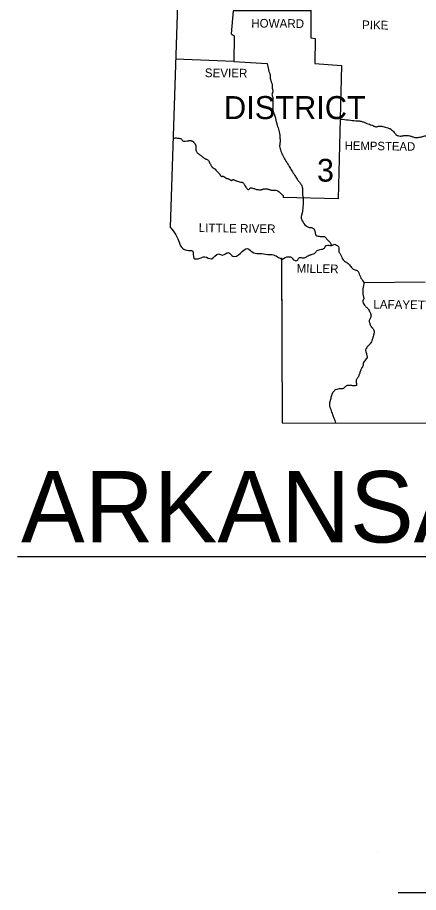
# Model space of a CAD drawing. Extents: x 164 to 3385, y 68 to 2119.
# Drawn here: x 2642.6 to 2834.9, y 1208.2 to 1627.9 of the extents above; entities that cross this region are included whole.
import ezdxf

# ---------------------------------------------------------------- set-up
doc = ezdxf.new("R2010")
doc.units = 0
for name, color, linetype in [('1', 7, 'Continuous'), ('2', 7, 'Continuous'), ('Default', 7, 'Continuous')]:
    doc.layers.add(name, color=color, linetype=linetype)

msp = doc.modelspace()

# ---------------------------------------------------------------- linework, layer by layer
at = {"layer": '1'}
for p, q in [((2642.58, 1369.37), (3267.14, 1369.37)), ((2815.36, 1227.78), (2815.36, 1227.78)), ((2825.14, 1208.22), (3138.23, 1208.22))]:
    msp.add_line(p, q, dxfattribs=at)
for points in [[(2769.26, 1512.61), (2769.46, 1433.46), (3128.04, 1432.87)], [(2769.26, 1511.75), (2769.46, 1433.46), (3124.12, 1432.88)]]:
    msp.add_lwpolyline(points, dxfattribs=at)
at = {"layer": 'Default'}
for points in [[(2704.43, 1950.7), (2724.46, 1789.87), (2715.75, 1527.33)], [(2811.49, 1730.41), (2811.36, 1690.77), (2806.52, 1690.68), (2806.91, 1687.77), (2802.26, 1687.87), (2802.16, 1685.74), (2797.62, 1685.74), (2797.71, 1684.19), (2790.94, 1684), (2790.84, 1678.1), (2784.26, 1678.68), (2783.2, 1631.07), (2745.94, 1631.16), (2745.07, 1620.13), (2746.42, 1619.16), (2746.33, 1606.78), (2718.43, 1608)], [(2783.2, 1631.07), (2783.2, 1618.2), (2785.33, 1617.81), (2785.13, 1605.81), (2797.91, 1604.84), (2796.36, 1540.88), (2770.04, 1541.55)], [(2746.33, 1606.78), (2762.39, 1605.81)], [(2769.26, 1511.75), (2769.46, 1433.46), (3124.12, 1432.88)], [(2838.16, 1501.01), (2808.84, 1500.72)]]:
    msp.add_lwpolyline(points, dxfattribs=at)
for points in [[(2762.39, 1605.81), (2762.88, 1602.91), (2763.06, 1602.27), (2763.3, 1601.64), (2763.55, 1601.02), (2763.75, 1600.39), (2763.81, 1599.91), (2763.81, 1599.42), (2763.8, 1598.93), (2763.84, 1598.45), (2764.04, 1597.73), (2764.3, 1597.01), (2764.56, 1596.29), (2764.71, 1595.55), (2764.71, 1594.49), (2764.77, 1593.95), (2764.86, 1593.42), (2764.95, 1592.89), (2765, 1592.36), (2764.95, 1592.06), (2764.82, 1591.78), (2764.68, 1591.49), (2764.62, 1591.2), (2764.7, 1590.62), (2764.87, 1590.04), (2765.04, 1589.46), (2765.1, 1588.87), (2765, 1587.13), (2765, 1585.68), (2765.1, 1583.26), (2765.23, 1582.71), (2765.45, 1582.19), (2765.69, 1581.67), (2765.88, 1581.13), (2766.65, 1577.94), (2767.13, 1576.29), (2767.91, 1573.78), (2768.39, 1570.68), (2768.49, 1568.36), (2768.46, 1567.83), (2768.38, 1567.29), (2768.31, 1566.76), (2768.29, 1566.23), (2768.88, 1563.81), (2769.94, 1561.39), (2771.29, 1559.07), (2772.94, 1556.46), (2774.1, 1554.42), (2775.55, 1552.2), (2776.71, 1550.36), (2777.13, 1549.77), (2777.57, 1549.2), (2778.03, 1548.63), (2778.46, 1548.04), (2779.23, 1546.1), (2779.27, 1545.42), (2779.25, 1544.75), (2779.21, 1544.07), (2779.23, 1543.39), (2779.33, 1542.76), (2779.45, 1542.14), (2779.57, 1541.51), (2779.62, 1540.88), (2779.52, 1538.07), (2779.33, 1535.55), (2779.19, 1534.68), (2778.98, 1533.8), (2778.77, 1532.94), (2778.65, 1532.07), (2779.13, 1530.42), (2780.97, 1528.01), (2782.13, 1527.33), (2782.63, 1527.21), (2783.16, 1527.19), (2783.68, 1527.14), (2784.17, 1526.94), (2784.73, 1526.32), (2785.13, 1525.59), (2785.28, 1525.08), (2785.32, 1524.52), (2785.41, 1523.99), (2785.53, 1523.76), (2785.71, 1523.55), (2786.7, 1523.08), (2787.75, 1522.88), (2788.03, 1522.85), (2788.33, 1522.86), (2788.93, 1522.92), (2789.5, 1522.92), (2789.97, 1522.68), (2791.04, 1521.52), (2792.49, 1519.97), (2793.2, 1518.61)], [(2797.29, 1579.19), (2801.39, 1578.81), (2804.78, 1578.42), (2806.09, 1578.32), (2806.74, 1578.25), (2807.07, 1578.2), (2807.39, 1578.13), (2808.08, 1577.93), (2808.76, 1577.68), (2810.1, 1577.16), (2812.52, 1576.29), (2812.91, 1576.13), (2813.29, 1575.95), (2813.67, 1575.77), (2814.07, 1575.62), (2814.71, 1575.55), (2815.37, 1575.66), (2816.03, 1575.8), (2816.68, 1575.81), (2817.79, 1575.6), (2818.91, 1575.33), (2820.19, 1574.98), (2820.82, 1574.76), (2821.12, 1574.62), (2821.42, 1574.46), (2822.39, 1573.68), (2823.26, 1572.81), (2823.54, 1572.5), (2823.79, 1572.17), (2824.42, 1571.55), (2824.96, 1571.26), (2825.52, 1571.11), (2826.65, 1571.07), (2827.11, 1571.12), (2827.57, 1571.22), (2828.03, 1571.32), (2828.49, 1571.36), (2830.71, 1571.16), (2831.35, 1570.99), (2831.97, 1570.76), (2832.59, 1570.53), (2833.23, 1570.39), (2833.73, 1570.35), (2834.25, 1570.35), (2835.26, 1570.49), (2836.9, 1570.87), (2838.84, 1571.36), (2840.05, 1571.55), (2840.66, 1571.57), (2841.26, 1571.55), (2841.72, 1571.48), (2842.18, 1571.37), (2842.63, 1571.25), (2843.1, 1571.16), (2844.31, 1571.09), (2845.52, 1571.07), (2846.22, 1571.12), (2846.92, 1571.24), (2847.62, 1571.34), (2847.97, 1571.36), (2848.32, 1571.36), (2849.04, 1571.27), (2851.15, 1570.66), (2852.52, 1570.07), (2853.87, 1569.46)], [(2717.17, 1570.04), (2718.14, 1570.13), (2719.14, 1570.11), (2720.08, 1570), (2720.88, 1569.81), (2721.23, 1569.54), (2721.55, 1569.1), (2721.91, 1568.7), (2722.33, 1568.55), (2723.2, 1568.65), (2724.75, 1568.84), (2725.11, 1568.87), (2725.47, 1568.87), (2725.84, 1568.83), (2726.2, 1568.75), (2726.51, 1568.6), (2726.78, 1568.4), (2727.03, 1568.15), (2727.26, 1567.87), (2727.56, 1567.51), (2727.81, 1567.14), (2728.01, 1566.75), (2728.14, 1566.33), (2728.15, 1565.96), (2728.11, 1565.6), (2728.05, 1565.24), (2728.04, 1564.87), (2728.14, 1564.29), (2728.25, 1563.95), (2728.39, 1563.61), (2728.81, 1563.04), (2729.97, 1562.07), (2731.23, 1561.1), (2732.39, 1560.33), (2732.65, 1560.18), (2732.92, 1560.05), (2733.47, 1559.8), (2733.97, 1559.5), (2734.33, 1559.07), (2734.52, 1558.68), (2735.3, 1557.13), (2735.73, 1556.47), (2735.98, 1556.16), (2736.26, 1555.88), (2736.54, 1555.66), (2736.85, 1555.49), (2737.15, 1555.32), (2737.43, 1555.1), (2738.68, 1553.75), (2739.26, 1553.17), (2739.52, 1552.84), (2739.73, 1552.48), (2739.95, 1552.12), (2740.08, 1551.96), (2740.23, 1551.81), (2740.47, 1551.72), (2740.75, 1551.73), (2741.04, 1551.76), (2741.3, 1551.71), (2741.66, 1551.51), (2742.02, 1551.27), (2742.37, 1551.03), (2742.75, 1550.84), (2743.01, 1550.76), (2743.28, 1550.69), (2743.55, 1550.63), (2743.81, 1550.55), (2744.11, 1550.39), (2744.39, 1550.16), (2744.67, 1549.94), (2744.97, 1549.78), (2745.26, 1549.81), (2745.55, 1549.97), (2745.85, 1550.14), (2746.13, 1550.17), (2746.5, 1550.03), (2746.86, 1549.87), (2747.22, 1549.72), (2747.59, 1549.59), (2749.52, 1549), (2749.79, 1548.96), (2750.07, 1548.95), (2750.46, 1548.88), (2750.53, 1548.85), (2750.59, 1548.81), (2750.99, 1548.41), (2751.29, 1547.94), (2751.55, 1547.45), (2751.69, 1547.2), (2751.84, 1546.97), (2752.44, 1546.17), (2752.76, 1545.79), (2753.1, 1545.42), (2753.27, 1545.35), (2753.45, 1545.4), (2753.83, 1545.74), (2754.23, 1546.14), (2754.44, 1546.27), (2754.65, 1546.29), (2755.37, 1546.11), (2756.09, 1545.84), (2756.81, 1545.59), (2757.55, 1545.42), (2758.47, 1545.33), (2759.39, 1545.33), (2759.81, 1545.42), (2760.21, 1545.58), (2760.62, 1545.73), (2761.04, 1545.81), (2762.3, 1545.71), (2762.88, 1545.58), (2763.46, 1545.42), (2764.04, 1545.26), (2764.62, 1545.13), (2764.98, 1545.11), (2765.34, 1545.13), (2765.71, 1545.16), (2766.07, 1545.13), (2767.62, 1544.55), (2769.07, 1543.39), (2770.04, 1542.13), (2770.04, 1541.55)], [(2715.75, 1527.33), (2718.56, 1523.65), (2719.72, 1521.04), (2721.36, 1517.65), (2723.78, 1516.3), (2726.59, 1515.81), (2727.17, 1512.52), (2730.07, 1512.43), (2732.39, 1513.1), (2735.59, 1512.23), (2738.97, 1514.55), (2740.91, 1513.97), (2743.72, 1515.13), (2745.84, 1513.39), (2749.52, 1514.94), (2752.81, 1517.07), (2755.91, 1515.04), (2758.91, 1514.75), (2762.49, 1514.26), (2765.3, 1514.07), (2767.81, 1512.81), (2769.08, 1511.94), (2769.26, 1511.75)], [(2769.26, 1511.75), (2772.65, 1513.2), (2774.1, 1512.72), (2775.36, 1511.46), (2776.81, 1511.46), (2777.58, 1512.62), (2779.04, 1512.72), (2780.2, 1512.62), (2781.46, 1513.39), (2782.52, 1513.88), (2783.97, 1514.36), (2785.04, 1514.75), (2786, 1515.81), (2787.75, 1516.68), (2789.78, 1517.36), (2790.36, 1518.33), (2791.33, 1518.72), (2793.26, 1518.62), (2794.52, 1519.2), (2795.58, 1518.72), (2796.55, 1518.04), (2796.75, 1515.52), (2797.52, 1514.17), (2798.68, 1511.75), (2800.33, 1510.49), (2801.87, 1509.23), (2802.45, 1508.46), (2804.1, 1507.01), (2805.55, 1506.52), (2806.23, 1505.46), (2807.29, 1502.94), (2808.84, 1500.72)], [(2808.84, 1500.72), (2808.51, 1499.47), (2808.37, 1498.68), (2808.26, 1497.91), (2808.16, 1495.68), (2808.24, 1495.02), (2808.39, 1494.36), (2808.55, 1493.71), (2808.65, 1493.07), (2808.58, 1492.75), (2808.4, 1492.44), (2808.22, 1492.13), (2808.16, 1491.81), (2808.25, 1491.35), (2808.41, 1490.89), (2808.94, 1489.97), (2809.29, 1489.56), (2809.67, 1489.22), (2810.04, 1488.89), (2810.39, 1488.52), (2810.95, 1487.79), (2811.45, 1486.97), (2811.72, 1486.42), (2811.91, 1485.86), (2812.05, 1485.3), (2812.13, 1484.75), (2812.02, 1484.12), (2811.69, 1483.49), (2811.37, 1482.86), (2811.26, 1482.23), (2811.38, 1481.58), (2811.59, 1480.92), (2812.23, 1479.62), (2812.43, 1479.35), (2812.67, 1479.14), (2812.9, 1478.92), (2813.1, 1478.65), (2813.58, 1477.1), (2813.49, 1476.35), (2813.34, 1475.6), (2812.91, 1474.1), (2812.03, 1471.88), (2811.84, 1471.57), (2811.61, 1471.28), (2811.11, 1470.75), (2810.58, 1470.22), (2810.1, 1469.65), (2809.52, 1468.59), (2809.81, 1467.14), (2809.95, 1466.55), (2810.1, 1465.97), (2810.23, 1465.39), (2810.27, 1465.1), (2810.29, 1464.96), (2810.29, 1464.81), (2810.12, 1464.46), (2809.96, 1464.3), (2809.81, 1464.14), (2809.17, 1463.32), (2808.55, 1462.49), (2808.37, 1462.07), (2808.32, 1461.59), (2808.28, 1461.11), (2808.16, 1460.65), (2807.96, 1460.26), (2807.72, 1459.88), (2807.49, 1459.5), (2807.29, 1459.1), (2807.03, 1458.41), (2806.8, 1457.7), (2806.58, 1456.99), (2806.33, 1456.3), (2806.04, 1455.7), (2805.71, 1455.13), (2805.37, 1454.55), (2805.07, 1453.98), (2805.01, 1453.24), (2805.16, 1452.38), (2805.22, 1451.66), (2805.12, 1451.44), (2804.87, 1451.36), (2802.94, 1451.36), (2800.71, 1451.36), (2800.16, 1451.16), (2799.68, 1450.71), (2799.21, 1450.22), (2798.68, 1449.91), (2798.23, 1449.85), (2797.77, 1449.86), (2797.3, 1449.87), (2796.84, 1449.81), (2795.7, 1449.51), (2794.62, 1448.94), (2794.15, 1448.55), (2793.77, 1448.11), (2793.26, 1447.1), (2792.78, 1445.07), (2792.63, 1444.59), (2792.47, 1444.11), (2792.2, 1443.14), (2792.15, 1442.32), (2792.27, 1441.48), (2792.5, 1440.65), (2792.78, 1439.85), (2793.65, 1437.52), (2794.33, 1435.69), (2795.19, 1433.42)]]:
    msp.add_spline(points, degree=3, dxfattribs=at)

# ---------------------------------------------------------------- texts
at = {"layer": '2'}
msp.add_text('ARKANSAS HIGHWAY DISTRICT 7', height=34.244, dxfattribs=at).set_placement((2644.27, 1376.13))
at = {"layer": 'Default'}
for s, height, rotation, p in [('HOWARD', 4.162, 359.5145, (2754.65, 1623.13)), ('PIKE', 4.161, 359.0451, (2807.78, 1622.36)), ('SEVIER', 4.162, 359.4271, (2732.39, 1599.33)), ('HEMPSTEAD', 4.064, 359.1885, (2799.45, 1564.49)), ('LITTLE RIVER', 4.1618, 359.1697, (2729.49, 1525.01)), ('MILLER', 4.161, 359.1319, (2776.42, 1505.55)), ('LAFAYETTE', 4.161, 359.1839, (2813.2, 1488.33))]:
    msp.add_text(s, height=height, rotation=rotation, dxfattribs=at).set_placement(p)
for s, height, p in [('DISTRICT', 11.032, (2741.59, 1579.2)), ('3', 10.93, (2786.2, 1549.2))]:
    msp.add_text(s, height=height, dxfattribs=at).set_placement(p)

doc.saveas('drawing.dxf')
